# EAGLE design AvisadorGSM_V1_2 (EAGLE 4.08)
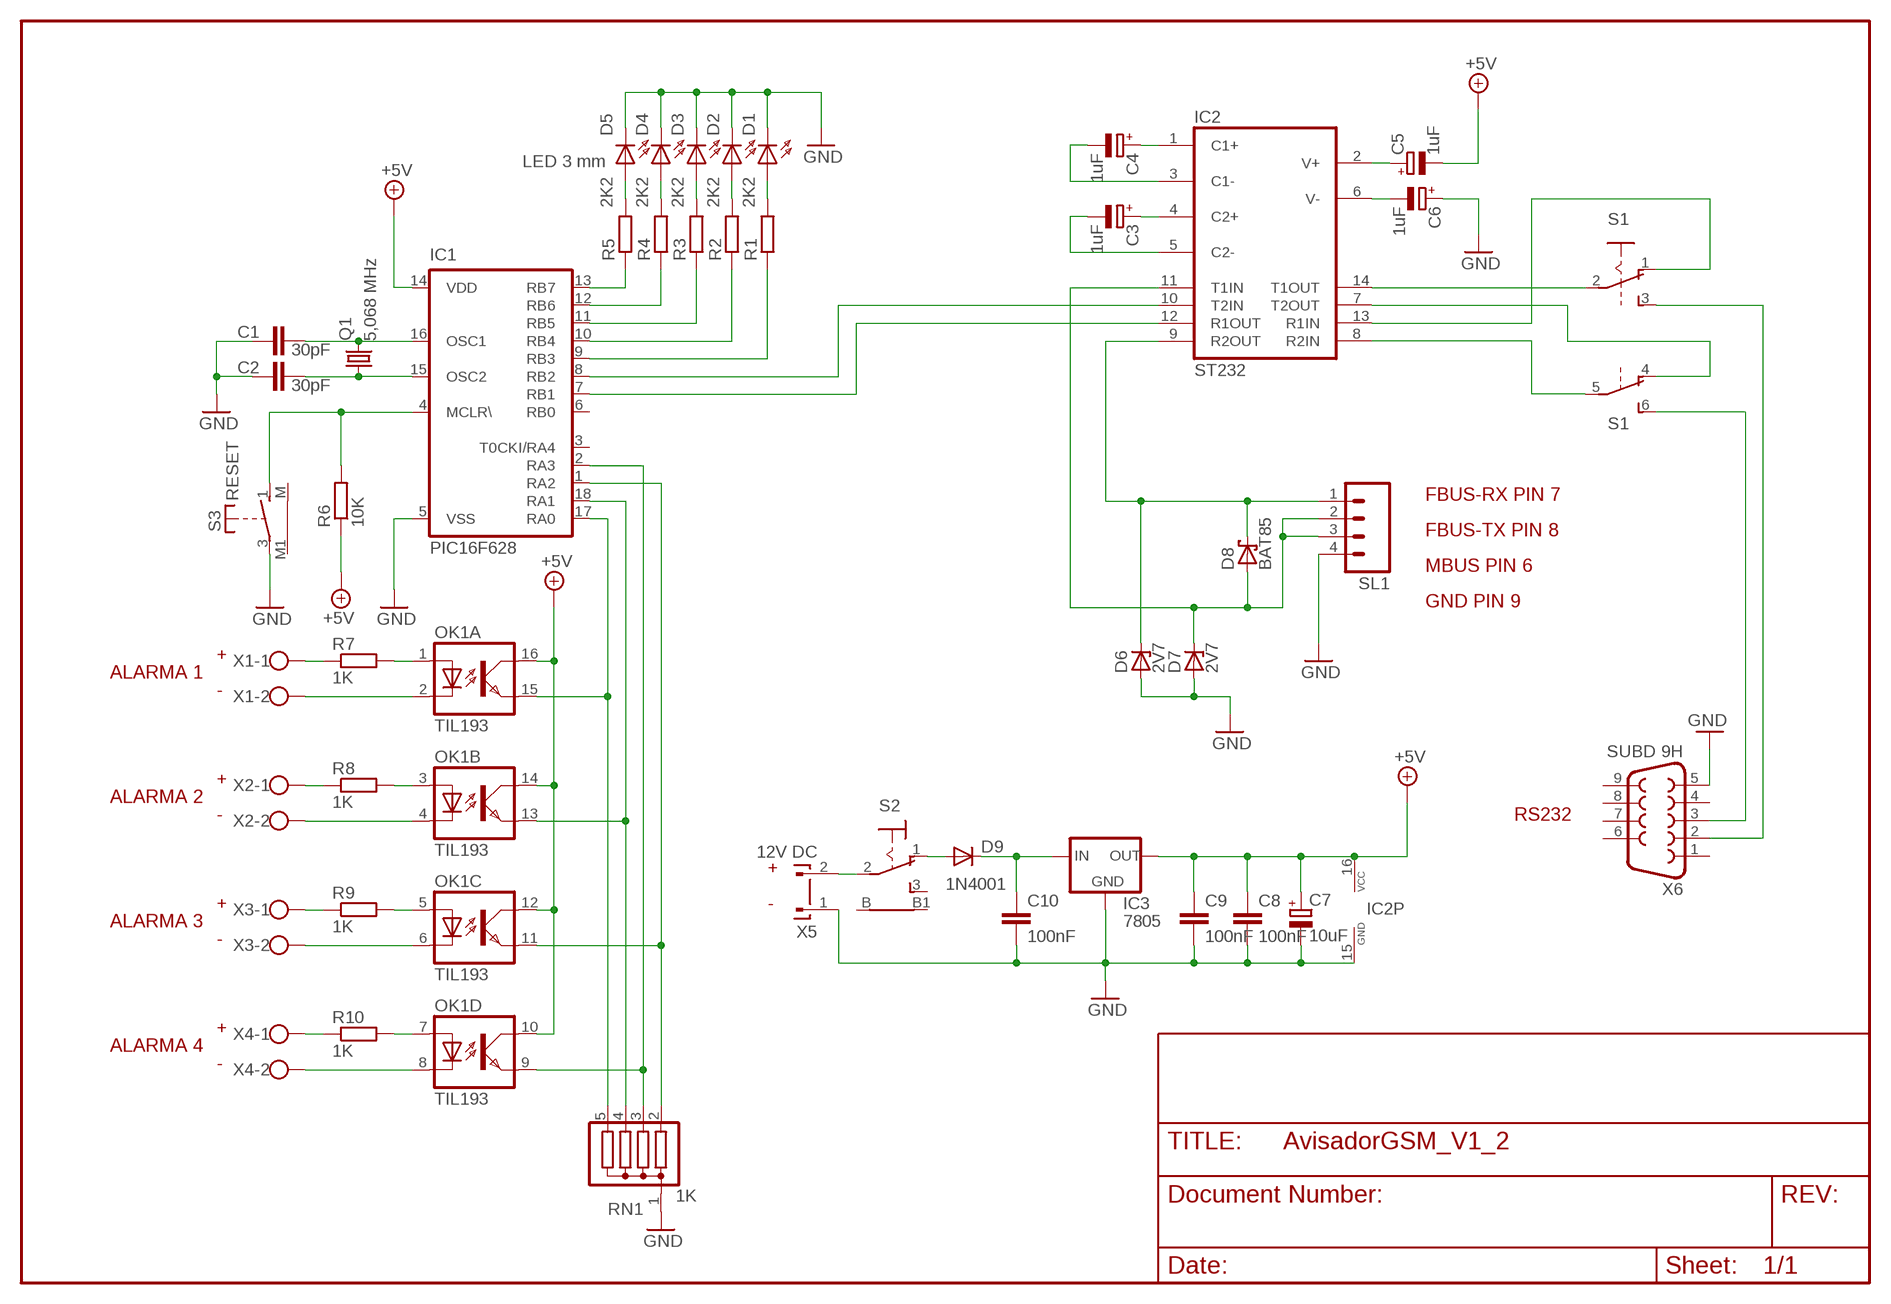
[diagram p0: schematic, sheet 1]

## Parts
C1  30pF  C-EU025-024X044  [C025-024X044]
C2  30pF  C-EU025-024X044  [C025-024X044]
C3  1uF  CPOL-EUE1.8-4  [E1,8-4]
C4  1uF  CPOL-EUE1.8-4  [E1,8-4]
C5  1uF  CPOL-EUE1.8-4  [E1,8-4]
C6  1uF  CPOL-EUE1.8-4  [E1,8-4]
C7  10uF  CPOL-EUE2-4  [E2-4]
C8  100nF  C-EU025-024X044  [C025-024X044]
C9  100nF  C-EU025-024X044  [C025-024X044]
C10  100nF  C-EU025-024X044  [C025-024X044]
D1  LED3MM  [LED3MM]
D2  LED3MM  [LED3MM]
D3  LED3MM  [LED3MM]
D4  LED3MM  [LED3MM]
D5  LED 3 mm  LED3MM  [LED3MM]
D6  2V7  ZENER-DIODEDO34-7  [DO34Z7]
D7  2V7  ZENER-DIODEDO34-7  [DO34Z7]
D8  BAT85  SCHOTTKY-DIODEDO35-7  [DO35-7]
D9  1N4001  1N4004  [DO41-10]
IC1  PIC16F628  PIC16F83P  [DIL18]
IC2  ST232  MAX232  [DIL16]
IC3  7805  78XXS  [78XXS]
OK1  TIL193  [DIL16]
Q1  5,068 MHz  HC49U-V  [HC49U-V]
R1  2K2  R-EU_0204/7  [0204/7]
R2  2K2  R-EU_0204/7  [0204/7]
R3  2K2  R-EU_0204/7  [0204/7]
R4  2K2  R-EU_0204/7  [0204/7]
R5  2K2  R-EU_0204/7  [0204/7]
R6  10K  R-EU_0204/7  [0204/7]
R7  1K  R-EU_0204/7  [0204/7]
R8  1K  R-EU_0204/7  [0204/7]
R9  1K  R-EU_0204/7  [0204/7]
R10  1K  R-EU_0204/7  [0204/7]
RN1  1K  G04R  [SIL5]
S1  A68-A31  [A68-A31]
S2  9070-1W  [9070-1W]
S3  RESET  TP33W  [TP33W]
SL1  M04  [04P]
X1  W237-102  [W237-102]
X2  W237-102  [W237-102]
X3  W237-102  [W237-102]
X4  W237-102  [W237-102]
X5  12V DC  2POL-PCB  [2POL-PCB]
X6  SUBD 9H  F09H  [F09H]

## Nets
+5V: C5.- C7.+ C8.1 C9.1 IC1.14(VDD) IC2.16(VCC) IC3.OUT OK1.10(D:COL) OK1.12(C:COL) OK1.14(B:COL) OK1.16(A:COL) R6.1
GND: C1.1 C2.1 C6.+ C7.- C8.2 C9.2 C10.2 D1.K(C) D2.K(C) D3.K(C) D4.K(C) D5.K(C) D6.A D7.A IC1.5(VSS) IC2.15(GND) IC3.GND RN1.1 S3.3(P) SL1.4 X5.1 X6.5
N$1: IC1.4(MCLR\) R6.2 S3.1(S)
N$2: C1.2 IC1.16(OSC1) Q1.2
N$3: C2.2 IC1.15(OSC2) Q1.1
N$4: C4.+ IC2.1(C1+)
N$5: C3.+ IC2.4(C2+)
N$6: C3.- IC2.5(C2-)
N$7: C4.- IC2.3(C1-)
N$8: C5.+ IC2.2(V+)
N$9: C6.- IC2.6(V-)
N$10: S1.6(B:S) X6.3
N$11: IC1.17(RA0) OK1.15(A:EMIT) RN1.5
N$12: IC2.14(T1OUT) S1.2(A:P)
N$13: IC2.8(R2IN) S1.5(B:P)
N$14: IC1.8(RB2) IC2.10(T2IN)
N$15: IC1.7(RB1) IC2.12(R1OUT)
N$16: D6.C D8.C IC2.9(R2OUT) SL1.1
N$17: IC1.13(RB7) R5.1
N$18: S1.3(A:S) X6.2
N$19: D5.A R5.2
N$20: IC1.1(RA2) OK1.11(C:EMIT) RN1.2
N$21: IC1.2(RA3) OK1.9(D:EMIT) RN1.3
N$22: IC1.18(RA1) OK1.13(B:EMIT) RN1.4
N$23: D9.A S2.1(O)
N$24: D7.C D8.A IC2.11(T1IN) SL1.2 SL1.3
N$25: S2.2(P) X5.2
N$26: IC1.12(RB6) R4.1
N$27: IC1.11(RB5) R3.1
N$28: IC1.10(RB4) R2.1
N$29: IC1.9(RB3) R1.1
N$30: D4.A R4.2
N$31: D3.A R3.2
N$32: D2.A R2.2
N$33: D1.A R1.2
N$34: IC2.13(R1IN) S1.1(A:O)
N$35: OK1.2(A:C) X1.2
N$36: IC2.7(T2OUT) S1.4(B:O)
N$37: OK1.4(B:C) X2.2
N$38: OK1.6(C:C) X3.2
N$39: C10.1 D9.C IC3.IN
N$40: R7.1 X1.1
N$41: OK1.8(D:C) X4.2
N$42: OK1.1(A:A) R7.2
N$43: R8.1 X2.1
N$45: OK1.3(B:A) R8.2
N$47: R9.1 X3.1
N$48: OK1.5(C:A) R9.2
N$50: R10.1 X4.1
N$51: OK1.7(D:A) R10.2
Unconnected: IC1.3(T0CKI/RA4) IC1.6(RB0) S2.3(S) S2.B S2.B1 S3.M S3.M1(M) X6.1 X6.4 X6.6 X6.7 X6.8 X6.9

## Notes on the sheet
- FBUS-RX PIN 7
- FBUS-TX PIN 8
- MBUS PIN 6
- GND PIN 9
- +
- ALARMA 1
- -
- +
- ALARMA 2
- - | RS232
- +
- + | -
- ALARMA 3
- -
- +
- ALARMA 4
- -

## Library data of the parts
C1 C2 C8-C10 = rcl:C-EU: CAPACITOR, European symbol
C3-C7 = rcl:CPOL-EU: POLARIZED CAPACITOR, European symbol
D1-D5 = led:LED3MM: LED
D6 D7 = diode:ZENER-DIODE: Z-Diode
D8 = diode:SCHOTTKY-DIODE: Schottky Diode
D9 = diode:1N4004: DIODE
IC1 = microchip:PIC16F8*: MICROCONTROLLER 8-Bit PIC16F8X Family - CMOS Flash/EEPROM Pin Compatible : PIC16F83, PIC16CR83, PIC16F84A, PIC16CR84 see also PIC16C*
IC2 = maxim:MAX232: RS232 TRANSEIVER
IC3 = v-reg:78XXS: VOLTAGE REGULATOR
OK1 = optocoupler:TIL193: TEXAS INSTRUMENTS OPTO COUPLER
Q1 = crystal:HC49U-V: CRYSTAL
R1-R10 = rcl:R-EU_: RESISTOR, European symbol
RN1 = resistor-sil:G04R: SIL RESISTOR
S1 = switch:A68-A31: SLIDING SWITCH Siemens, distributor Buerklin, 11G766
S2 = switch:9070-1W: TOGGLE SWITCH Marquardt
S3 = switch-misc:TP33W: SWITCH
SL1 = con-amp-quick:M04: AMP QUICK CONNECTOR
X1-X4 = con-wago-500:W237-102: WAGO SCREW CLAMP
X5 = con-friwo:2POL-PCB: PCB SUPPLY CONNECTOR
X6 = con-subd:F09: SUB-D

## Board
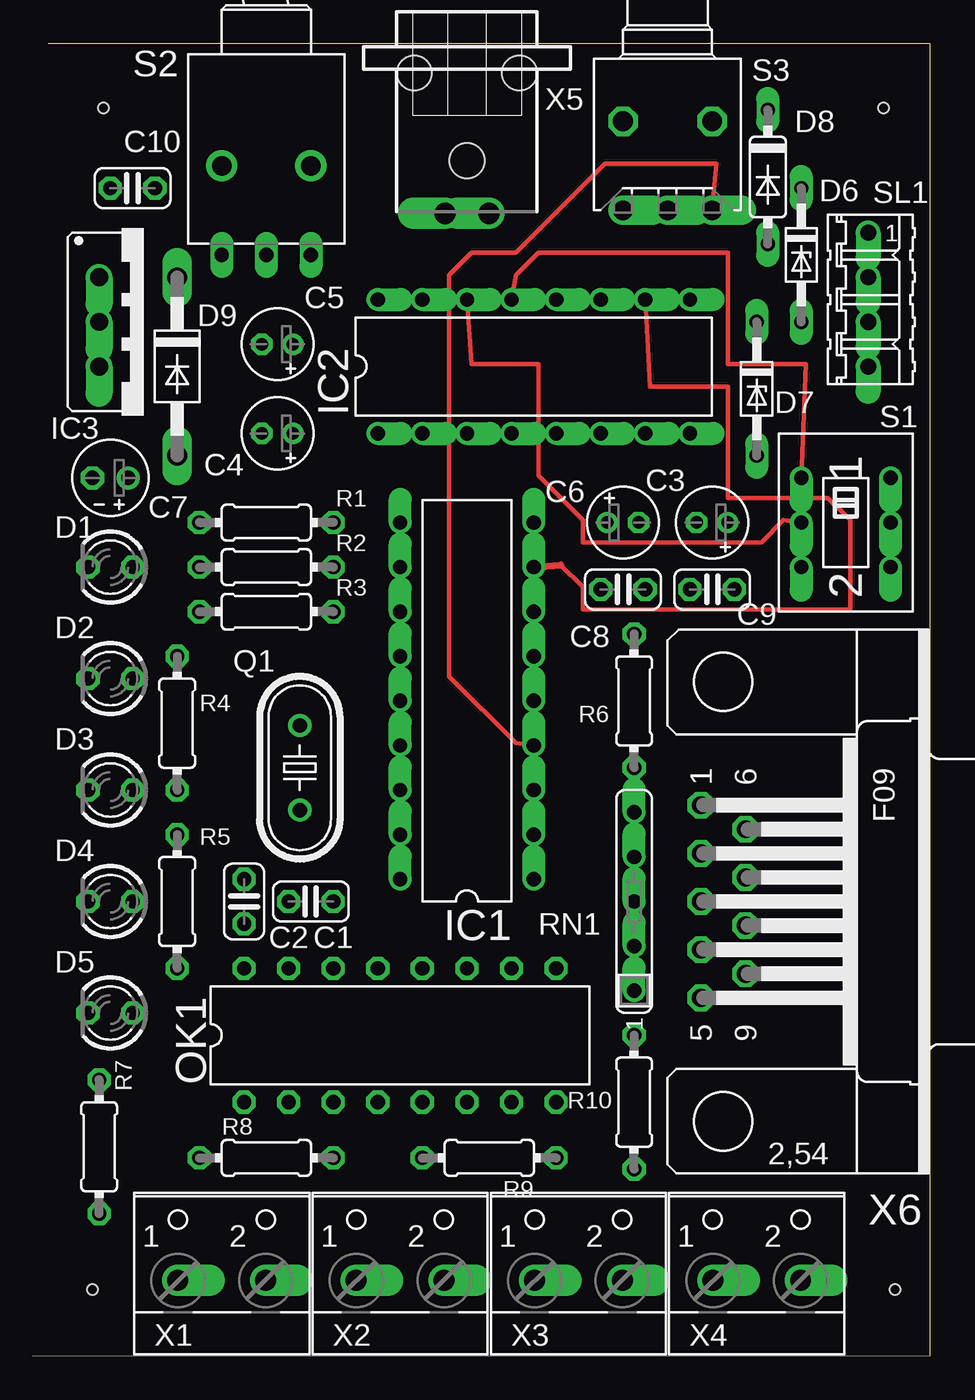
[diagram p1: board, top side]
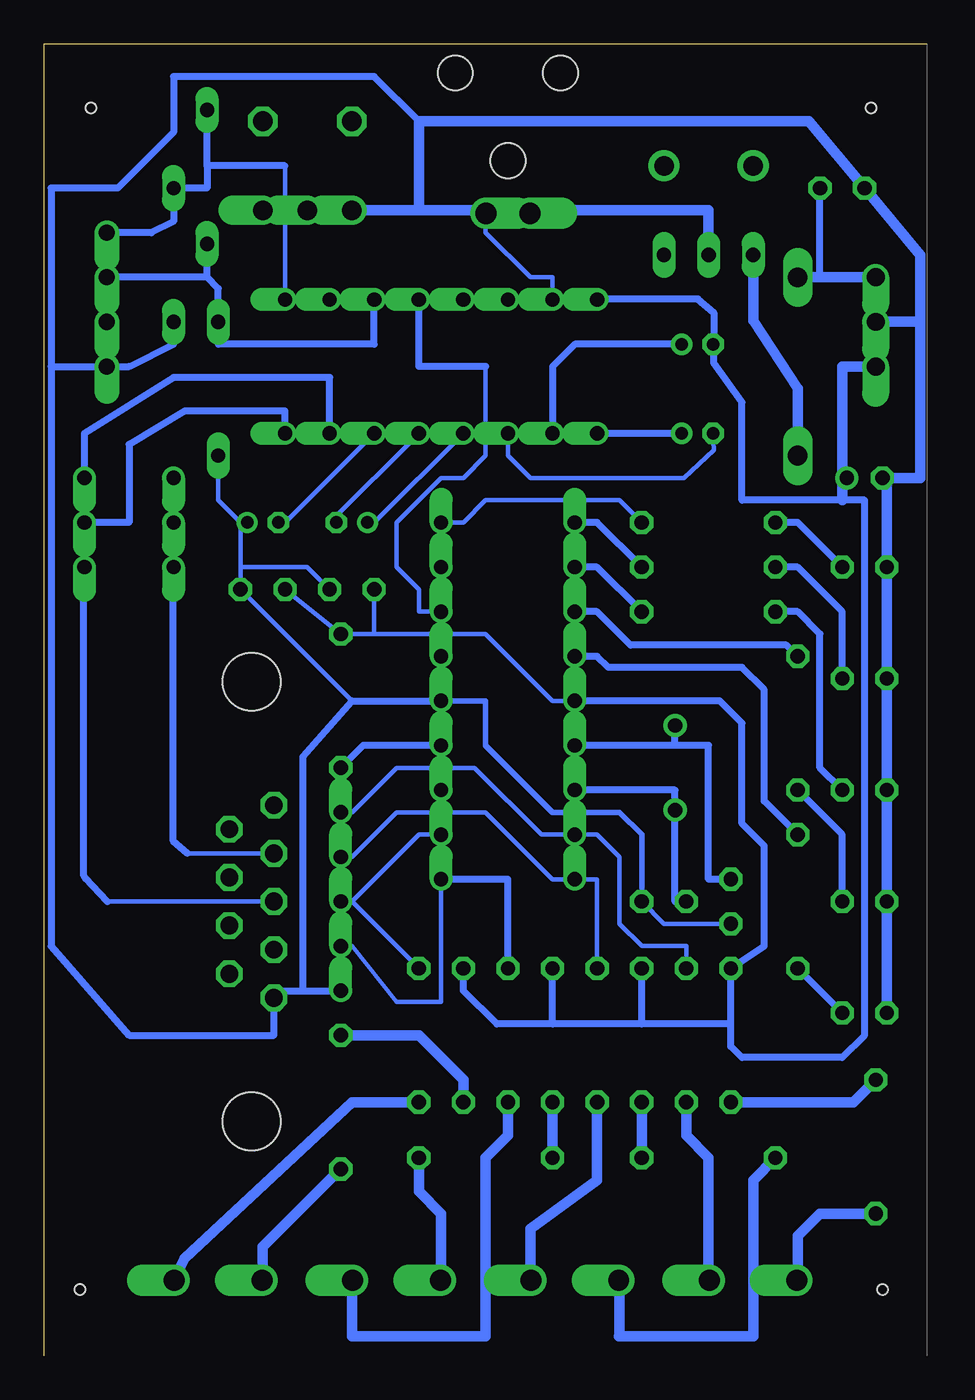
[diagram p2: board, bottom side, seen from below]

Size 50.28 x 74.73 mm. Coordinates in mm from the lower left corner, seen from the top.
Outline: 50.28,0 50.28,74.73 0,74.73
Copper layers used: Top, Bottom
Holes 0.61 mm at 3.17,71.08 2.54,3.77 48.25,3.77 47.62,71.08

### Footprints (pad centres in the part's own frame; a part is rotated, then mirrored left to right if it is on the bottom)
C025-024X044 = drill 0.813 octagon: 1 -1.27,0; 2 1.27,0
E1,8-4 = drill 0.711 pad 1.168 round: + -0.889,0 | drill 0.711 pad 1.168 octagon: - 0.889,0
E2-4 = drill 0.813 pad 1.27 round: + -1.016,0 | drill 0.813 pad 1.27 octagon: - 1.016,0
LED3MM = drill 0.813 octagon: A -1.27,0; K 1.27,0
DO34Z7 = drill 0.813 long: A 3.81,0; C -3.81,0
DO35-7 = drill 0.813 long: A 3.81,0; C -3.81,0
DO41-10 = drill 1.118 long: A 5.08,0; C -5.08,0
DIL18 = drill 0.813 offset: 1 -10.16,-3.81; 2 -7.62,-3.81; 3 -5.08,-3.81; 4 -2.54,-3.81; 5 0,-3.81; 6 2.54,-3.81; 7 5.08,-3.81; 8 7.62,-3.81; 9 10.16,-3.81; 10 10.16,3.81; 11 7.62,3.81; 12 5.08,3.81; 13 2.54,3.81; 14 0,3.81; 15 -2.54,3.81; 16 -5.08,3.81; 17 -7.62,3.81; 18 -10.16,3.81
DIL16 = drill 0.813 offset: 1 -8.89,-3.81; 2 -6.35,-3.81; 3 -3.81,-3.81; 4 -1.27,-3.81; 5 1.27,-3.81; 6 3.81,-3.81; 7 6.35,-3.81; 8 8.89,-3.81; 9 8.89,3.81; 10 6.35,3.81; 11 3.81,3.81; 12 1.27,3.81; 13 -1.27,3.81; 14 -3.81,3.81; 15 -6.35,3.81; 16 -8.89,3.81
78XXS = drill 1.016 offset: GND 0,-2.54; IN -2.54,-2.54; OUT 2.54,-2.54
DIL16' = drill 0.813 octagon: 1 -8.89,-3.81; 2 -6.35,-3.81; 3 -3.81,-3.81; 4 -1.27,-3.81; 5 1.27,-3.81; 6 3.81,-3.81; 7 6.35,-3.81; 8 8.89,-3.81; 9 8.89,3.81; 10 6.35,3.81; 11 3.81,3.81; 12 1.27,3.81; 13 -1.27,3.81; 14 -3.81,3.81; 15 -6.35,3.81; 16 -8.89,3.81
HC49U-V = drill 0.813 round: 1 -2.413,0; 2 2.413,0
0204/7 = drill 0.813 octagon: 1 -3.81,0; 2 3.81,0
SIL5 = drill 0.813 offset: 1 -5.08,0; 2 -2.54,0; 3 0,0; 4 2.54,0; 5 5.08,0
A68-A31 = drill 0.813 offset: 1 -2.54,-2.54; 2 0,-2.54; 3 2.54,-2.54; 4 -2.54,2.54; 5 0,2.54; 6 2.54,2.54
9070-1W = drill 0.813 long: 1 5.08,-2.54; 2 5.08,0; 3 5.08,2.54 | drill 1.118 pad 1.778 round: B 0,-2.54; B1 0,2.54
TP33W = drill 1.118 offset: 1 2.54,-5.08; 2 0,-5.08; 3 -2.54,-5.08 | drill 1.118 octagon: M 2.54,0; M1 -2.54,0
04P = drill 0.914 offset: 1 -3.81,0; 2 -1.27,0; 3 1.27,0; 4 3.81,0
W237-102 = drill 1.194 offset: 1 -2.5,-1.27; 2 2.5,-1.27
2POL-PCB = drill 1.2 offset: 1 -1.25,11.6; 2 1.25,11.6 | hole 2: -3,3.6; 3,3.6; 0,8.6
F09H = drill 1.016 octagon: 1 -5.486,-1.27; 2 -2.743,-1.27; 3 0,-1.27; 4 2.743,-1.27; 5 5.486,-1.27; 6 -4.115,1.27; 7 -1.372,1.27; 8 1.372,1.27; 9 4.115,1.27 | hole 3.302: -12.522,0; 12.522,0

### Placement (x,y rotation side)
C1  14.98,25.87 180 top
C2  11.17,25.87 90 top
C3  32.76,47.46 0 top
C4  13.08,52.54 180 top
C5  13.08,57.62 180 top
C6  37.84,47.46 180 top
C7  3.55,50 180 top
C8  32.76,43.65 0 top
C9  37.84,43.65 0 top
C10  4.82,66.51 180 top
D1  3.55,44.92 180 top
D2  3.55,38.57 180 top
D3  3.55,32.22 180 top
D4  3.55,25.87 180 top
D5  3.55,19.52 180 top
D6  42.92,62.7 270 top
D7  40.38,55.08 270 top
D8  41.02,67.15 270 top
D9  7.36,56.35 270 top
IC1  23.87,37.3 90 top
IC2  27.68,56.35 0 top
IC3  5.46,58.89 270 top
OK1  TIL193  [DIL16']  20.06,18.25 0 top
Q1  14.35,33.49 270 top
R1  12.44,47.46 180 top
R2  12.44,44.92 180 top
R3  12.44,42.38 180 top
R4  7.36,36.03 270 top
R5  7.36,25.87 270 top
R6  33.4,37.3 270 top
R7  2.92,11.9 90 top
R8  12.44,11.27 0 top
R9  25.14,11.27 180 top
R10  33.4,14.44 90 top
RN1  33.4,25.87 90 top
S1  45.46,47.46 270 top
S2  12.44,67.78 270 top
S3  35.3,70.32 0 top
SL1  46.73,60.16 270 top
U$1  [A4-SMALL-DOCFIELD]  not placed on the board
X1  9.9,5.55 0 top
X2  20.06,5.55 0 top
X3  30.22,5.55 0 top
X4  40.38,5.55 0 top
X5  23.87,76.67 180 top
X6  38.48,25.87 270 top

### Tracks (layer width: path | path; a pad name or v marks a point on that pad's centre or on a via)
+5V
  Bottom 0.254: 31.49,41.11 25.14,41.11 21.33,37.3 IC1.14 | 31.49,41.11 R6.1 C9.1 | 31.49,41.11 C8.1
  Bottom 0.406: 11.17,18.88 OK1.16 9.27,23.33 9.27,29.04 10.54,30.32 10.54,36.03 11.81,37.3 IC1.14 | IC2.16 18.79,60.19 13.04,60.19 12.14,59.42 12.14,57.64 | 11.17,18.88 16.25,18.88 | 16.25,18.88 21.33,18.88 | 21.33,18.88 24.51,18.88 26.41,20.79 OK1.10 | 21.33,18.88 OK1.12 | 16.25,18.88 OK1.14 | 11.17,18.88 11.17,17.61 10.54,16.98 4.82,16.98 3.55,18.25 3.55,48.73 4.82,48.73 10.54,48.73 10.54,54.31 12.14,56.55 12.14,57.64 | 12.14,57.64 12.14,57.62 C5.-
  Bottom 0.61: IC3.OUT 4.82,56.35 4.82,50 | 4.82,50 C7.+ | 4.82,48.73 4.82,50
GND
  Bottom 0.254: 2.28,50 C7.- | D1.K D2.K D3.K D4.K D5.K | 39.11,44.92 C9.2 32.76,37.3 | 39.11,44.92 39.11,47.46 | C8.2 35.3,44.92 39.11,44.92 | 39.11,47.46 40.38,48.73 D7.A | 39.11,47.46 C6.+ | IC2.15 21.33,61.43 22.6,61.43 25.14,63.97 X5.1 25.14,65.24 | C2.1 14.98,24.6 C1.1
  Bottom 0.305: IC1.5 25.14,37.3 25.14,34.76 21.33,30.95 17.52,30.95 16.25,29.68 16.24,29.68 16.24,25.87 | 16.24,25.84 16.24,25.87 | 16.24,25.87 C1.1
  Bottom 0.406: 49.91,56.35 SL1.4 45.46,56.35 42.92,57.62 D6.A | 35.55,20.79 37.21,20.79 37.21,18.25 | 35.55,20.79 RN1.1 | 37.21,18.25 45.46,18.25 49.91,23.33 49.91,56.35 | 49.91,56.35 49.91,66.51 46.1,66.51 42.92,69.69 42.92,72.86 31.49,72.86 28.95,70.32 | 37.21,18.25 X6.5 | IC1.5 32.76,37.3 35.55,34.12 35.55,20.79
  Bottom 0.61: 0.38,58.89 IC3.GND | 0.38,58.89 0.38,50 2.28,50 D1.K D5.K | 28.95,65.24 25.14,65.24 | 28.95,65.24 S3.3 | 28.95,65.24 28.95,70.32 6.73,70.32 C10.2 0.38,62.7 0.38,58.89
N$1
  Top 0.254: IC1.4 26.67,34.89 22.86,38.7 22.86,61.56 24.12,62.83 26.67,62.83 31.75,67.91 38.09,67.91 S3.1
  Bottom 0.406: R6.2 32.13,34.76 IC1.4
N$2
  Bottom 0.406: IC1.16 14.35,32.22 Q1.2 | Q1.2 14.35,30.95 | Q1.2 14.35,25.87 C1.2
N$3
  Bottom 0.254: Q1.1 14.35,36.03
  Bottom 0.406: 14.35,34.76 IC1.15 | 14.35,34.76 Q1.1 | 14.35,34.76 12.44,34.76 12.44,27.14 C2.2
N$4
  Bottom 0.406: 14.35,52.54 C4.+ IC2.1
N$5
  Bottom 0.254: IC2.4 31.49,47.46 C3.+
N$6
  Bottom 0.254: IC2.5 34.03,47.46 C3.-
N$7
  Bottom 0.254: C4.- 12.14,51.59 13.84,50 22.6,50 23.87,51.27 IC2.3
N$8
  Bottom 0.406: C5.+ 20.06,57.62 21.33,56.35 IC2.2
N$9
  Bottom 0.254: IC2.6 36.57,47.46 C6.-
N$10
  Bottom 0.254: X6.3 46.7,25.87
  Bottom 0.406: S1.6 48.04,44.92 48.04,27.34 47.94,27.17 46.7,25.87
N$11
  Bottom 0.254: OK1.15 13.71,23.33 16.25,23.33 17.52,24.6 17.52,28.41 18.79,29.68 IC1.17 21.97,29.68 25.78,33.49 30.22,33.49 32.76,30.95 RN1.5
N$12
  Top 0.254: IC2.14 24.12,56.48 27.94,56.48 27.94,50.13 30.48,47.59 30.48,46.32 40.63,46.32 41.9,47.59 S1.2
N$13
  Bottom 0.406: S1.5 45.46,47.46 45.46,51.91 42.29,53.81 36.57,53.81 IC2.8
N$14
  Top 0.254: 29.21,45.05 30.48,43.78 30.48,42.51 45.71,42.51 45.71,47.59 44.45,48.86 38.73,48.86 38.73,55.21 34.28,55.21 IC2.10
  Top 0.406: IC1.8 29.21,45.05
N$15
  Bottom 0.254: 25.14,56.35 25.14,51.27 26.41,50 27.68,50 30.22,47.46 30.22,44.92 28.95,43.65 28.95,42.38 IC1.7
  Bottom 0.406: IC2.12 28.95,56.35 25.14,56.35
N$16
  Bottom 0.254: IC2.9 36.57,67.78
  Bottom 0.406: 36.57,67.78 41.02,67.78 | 41.02,67.78 D8.C | 41.02,67.78 41.02,66.51 D6.C 42.92,64.61 44.19,63.97 SL1.1
N$17
  Bottom 0.406: IC1.13 18.79,39.84 18.16,39.21 10.54,39.21 9.27,37.94 9.27,31.59 R5.1
N$18
  Bottom 0.254: 42.12,28.61 37.94,28.61 X6.2
  Bottom 0.406: S1.3 42.94,44.82 42.94,29.31 | 42.12,28.61 42.94,29.31 | 42.94,29.31 42.94,29.34
N$19
  Bottom 0.406: D5.A R5.2
N$20
  Bottom 0.254: IC1.1 27.68,20.16 30.22,20.16 32.76,23.33 RN1.2
  Bottom 0.406: IC1.1 23.87,27.14 OK1.11
N$21
  Bottom 0.254: 32.76,25.87 28.95,29.68 IC1.2 | OK1.9 32.76,25.87 | 32.76,25.87 RN1.3
N$22
  Bottom 0.254: OK1.13 18.79,27.14 IC1.18 21.33,27.14 25.14,30.95 30.22,30.95 32.76,28.41 RN1.4
N$23
  Bottom 0.61: S2.1 9.9,58.96 7.36,55.08 D9.A
N$24
  Bottom 0.406: IC2.11 31.49,57.62 40.38,57.62 D7.C 40.38,60.8 41.02,61.43 | 41.02,61.43 D8.A | 41.02,61.43 SL1.2 SL1.3
N$25
  Bottom 0.254: 22.6,65.24 X5.2
  Bottom 0.61: S2.2 12.44,65.24 22.6,65.24
N$26
  Bottom 0.406: IC1.12 18.79,42.38 16.89,40.48 8,40.48 R4.1
N$27
  Bottom 0.406: IC1.11 18.79,44.92 R3.1
N$28
  Bottom 0.406: R2.1 18.79,47.46 IC1.10
N$29
  Bottom 0.254: R1.1 17.52,48.73 25.14,48.73 26.41,47.46 IC1.9
N$30
  Bottom 0.406: D4.A 4.82,29.68 R4.2
N$31
  Bottom 0.406: R3.2 7.36,42.38 6.09,41.11 6.09,33.49 D3.A
N$32
  Bottom 0.406: R2.2 7.36,44.92 4.82,42.38 D2.A
N$33
  Bottom 0.406: R1.2 7.36,47.46 D1.A
N$34
  Top 0.254: S1.1 43.17,56.48 38.73,56.48 38.73,62.83 27.94,62.83 26.67,61.56 IC2.13
N$35
  Bottom 0.61: X1.2 12.44,4.28 12.44,11.27 13.71,12.54 OK1.2
N$36
  Bottom 0.406: S1.4 48,52.54 42.92,55.72 34.03,55.72 IC2.7
N$37
  Bottom 0.61: OK1.4 18.79,9.99 22.6,7.22 22.6,4.28 X2.2
N$38
  Bottom 0.61: X3.2 32.76,4.28 32.76,1.1 25.14,1.1 25.14,11.27 23.87,12.54 OK1.6
N$39
  Bottom 0.406: IC3.IN 3.55,61.43 | 6.09,61.43 C10.1
  Bottom 0.61: IC3.IN 6.09,61.43 D9.C
N$40
  Bottom 0.406: X1.1 7.36,4.28
  Bottom 0.61: 7.36,4.28 7.36,6.82 6.09,8.09 R7.1
N$41
  Bottom 0.61: OK1.8 32.76,14.44 42.29,5.55 42.92,4.28 X4.2
N$42
  Bottom 0.61: OK1.1 4.19,14.44 R7.2
N$43
  Bottom 0.61: 17.52,1.1 17.56,1.1 | X2.1 17.52,4.28 17.52,1.1 | 17.52,1.1 9.9,1.1 9.9,9.99 R8.1
N$45
  Bottom 0.61: R8.2 OK1.3
N$47
  Bottom 0.406: X3.1 27.68,4.28
  Bottom 0.61: 27.68,4.28 27.68,8.09 28.95,9.36 R9.1
N$48
  Bottom 0.61: R9.2 OK1.5
N$50
  Bottom 0.406: X4.1 37.84,4.28
  Bottom 0.61: 37.84,4.28 37.84,6.18 R10.1
N$51
  Bottom 0.61: R10.2 28.95,18.25 26.41,15.71 OK1.7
